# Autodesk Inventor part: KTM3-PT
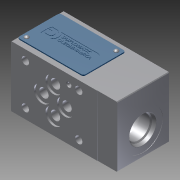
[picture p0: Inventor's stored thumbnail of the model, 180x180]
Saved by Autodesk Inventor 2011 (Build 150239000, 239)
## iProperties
Created: 2012-01
Part Number: KTM3-PT
Document SubType Name: Modeling
Designer: khramov
Density: 1 g/cm^3
Author: khramov
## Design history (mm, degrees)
derived "KTM3_PT_10N.iam"
node "Твердое тело1"
node "0134964.ipt:1"
sketch "3001110000.ipt:1"
sketch "0530521.ipt:1"
sketch "0530521.ipt:2"
